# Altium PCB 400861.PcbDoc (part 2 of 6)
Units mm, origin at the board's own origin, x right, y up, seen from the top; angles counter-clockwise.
Board outline 145 x 63.5 mm, 8 copper layers (Top Side, Mid-Layer 1, Mid-Layer 2, Mid-Layer 3, Mid-Layer 4, Mid-Layer 5, Mid-Layer 6, Bottom Side), stack 1.529 mm thick; 284 components, 233 nets, 1158 pads, 3522 vias.
Unrouted connection lines stored in the file: 1.
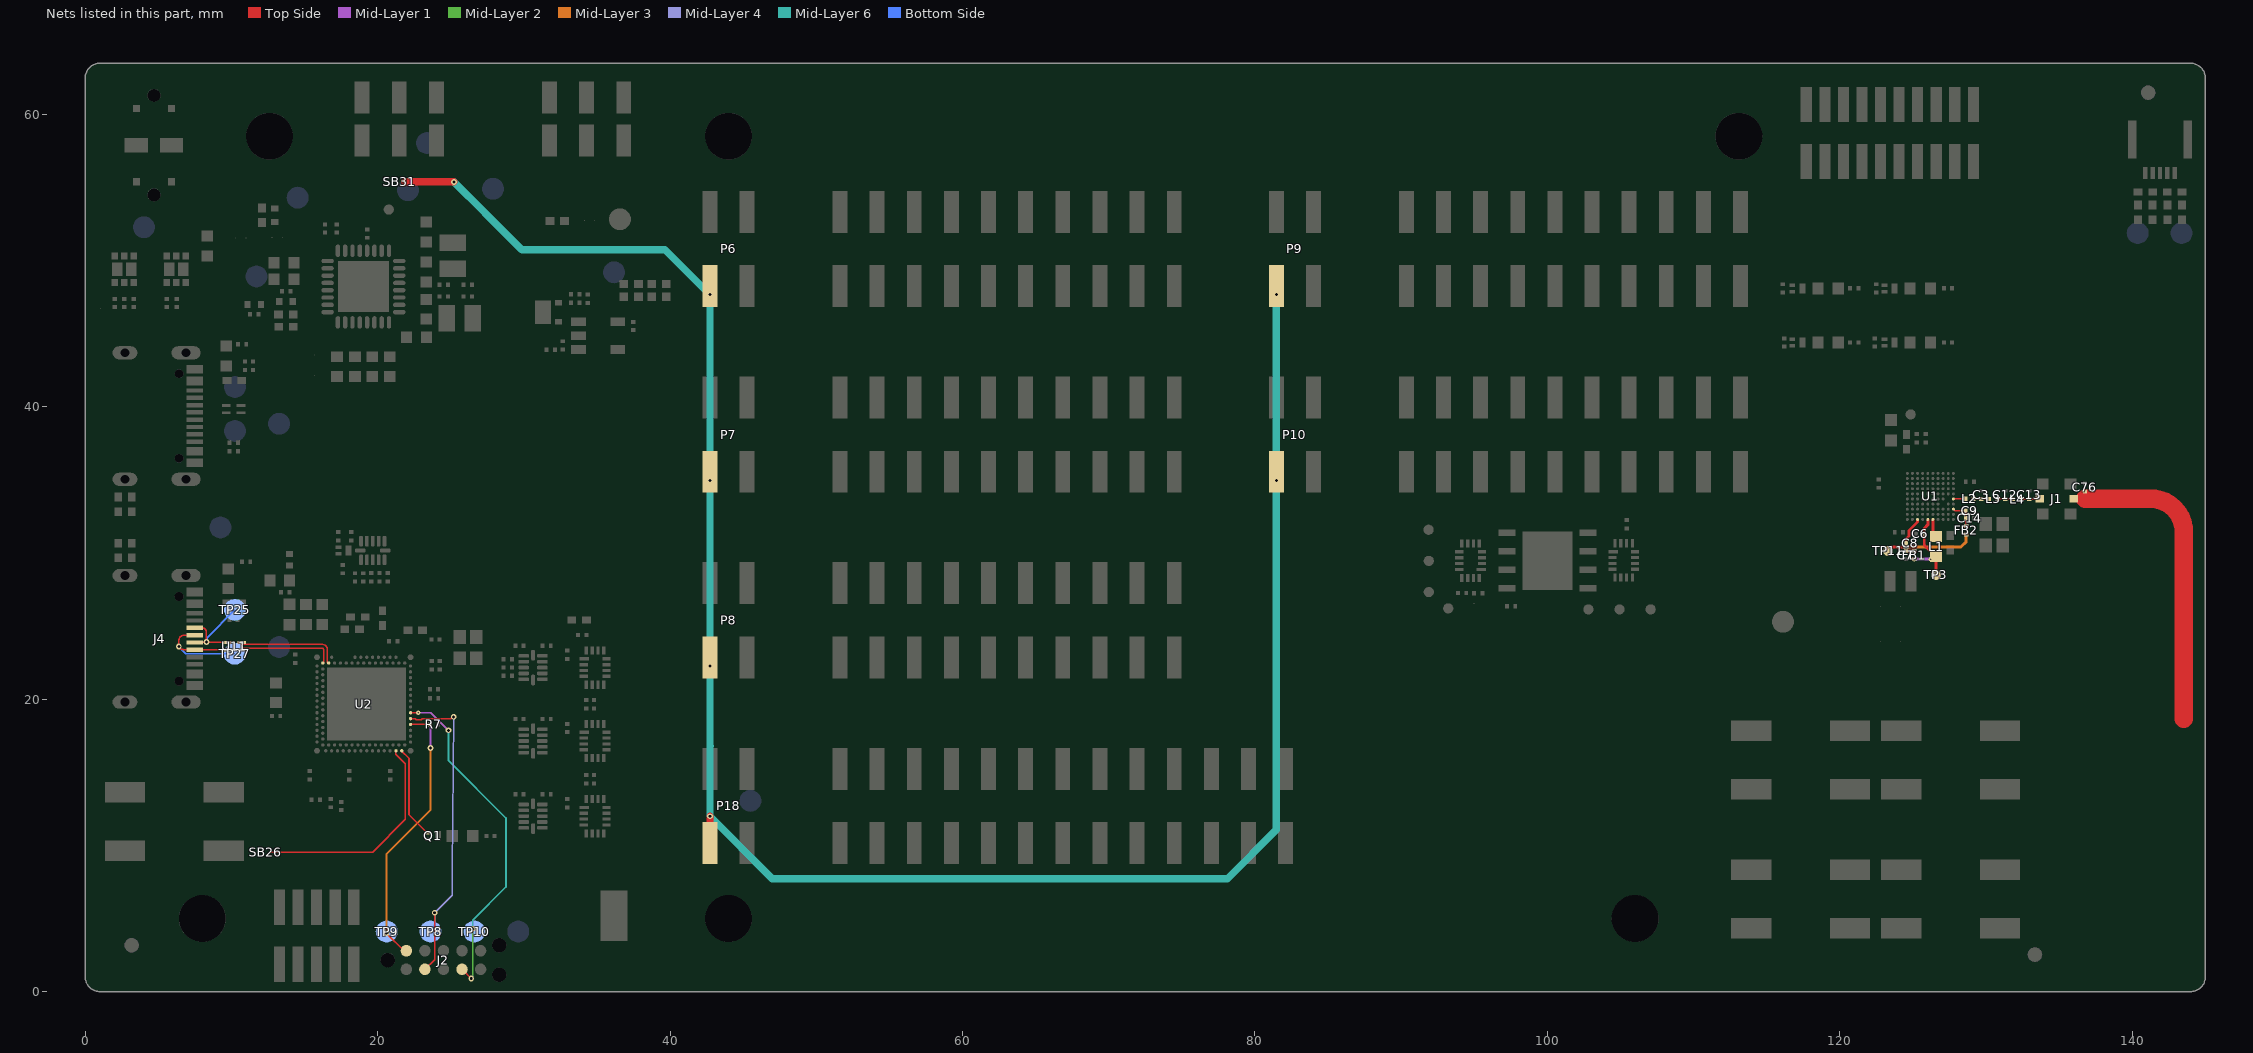
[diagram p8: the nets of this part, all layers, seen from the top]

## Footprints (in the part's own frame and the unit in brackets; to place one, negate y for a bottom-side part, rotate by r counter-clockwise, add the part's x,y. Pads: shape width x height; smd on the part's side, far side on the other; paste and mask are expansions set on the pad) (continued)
SON127P600X80_HS-9N [mm] "SON, 8-Leads, Body 5.00x6.00mm, Pitch 1.27mm, Thermal Pad 4.00x3.40mm, IPC Medium Density"
  rect 1.15x0.45 smd: 1(-2.77,1.905) 2(-2.77,0.635) 3(-2.77,-0.635) 4(-2.77,-1.905) 5(2.77,-1.905) 6(2.77,-0.635) 7(2.77,0.635) 8(2.77,1.905)
  rect 3.4x4 smd paste-1.7: 9(0,0)
  silkscreen extent -3.98,-2.6 3.1,2.67, body extent -3.05,-2.55 3.05,2.55, height 0.8
SOT95P280X145-5N [mm] "SOT23, 5-Leads, Body 2,90x2,80mm, Pitch 0,95mm, IPC Medium Density"
  rect 1x0.6 smd: 1(-1.35,0.95) 2(-1.35,0) 3(-1.35,-0.95) 4(1.35,-0.95) 5(1.35,0.95)
  silkscreen extent -1.45,-1.5 0.45,1.72, body extent -1.5,-1.55 1.5,1.55, height 1.45
Switch-PB-6.2x6.3mm-SMD [mm] "6.2×6.5mm TACT Switch, without ground connector"
  rect 2.75x1.4 smd: 1(-3.375,2) 1(3.375,2) 2(-3.375,-2) 2(3.375,-2)
  silkscreen extent -3,-3 3,3, body extent -3.6,-3.1 3.6,3.1, height 2.5
TC2050-IDC-NLFP [mil]
  round 39 hole 39 unplated: 0(-150,0) 0(150,-40) 0(150,40)
  round 31 smd paste-196.85: 1(-100,-25) 2(-50,-25) 3(0,-25) 4(50,-25) 5(100,-25) 6(100,25) 7(50,25) 8(0,25) 9(-50,25) 10(-100,25)
  Top Side pour cut-out: -100,25 -100,-25 100,-25 100,25
TP_SMD_D0.7mm [mm] "Test point - pad 0.7mm"
  round 0.7 smd paste-5: 1(0,0)
TP_SMD_D1.5mm [mm] "Test point - pad 1.5mm"
  round 1.5 smd paste-5: 1(0,0)
  body extent -0.75,-0.75 0.75,0.75, height 0.05
UFDFN50P120X250X55-8N [mm]
  round 0.025 smd: 1(-0.5,0.75) 4(-0.5,-0.75) 5(0.5,-0.75) 8(0.5,0.75)
  rect 0.6x0.2 smd: 2(-0.5,0.25) 3(-0.5,-0.25) 6(0.5,-0.25) 7(0.5,0.25)
  Top Side region: 0.4,0.85 0.8,0.85 0.8,0.65 0.2,0.65 0.2,1.05 0.4,1.05
  Top Side region: 0.8,-0.85 0.4,-0.85 0.4,-1.05 0.2,-1.05 0.2,-0.65 0.8,-0.65
  Top Side region: -0.2,0.65 -0.8,0.65 -0.8,0.85 -0.4,0.85 -0.4,1.05 -0.2,1.05
  Top Side region: -0.2,-1.05 -0.4,-1.05 -0.4,-0.85 -0.8,-0.85 -0.8,-0.65 -0.2,-0.65
  silkscreen extent -1.08,-1.37 0.6,1.37, body extent -0.6,-1.25 0.6,1.25, height 0.6
WEE_3x4.5mm [mm]
  silkscreen extent -1.47,-2.7 1.47,1.71
XQFN40P180X260X50-16N [mm] "QFN, 16-Leads, Body 1.80x2.60mm, Pitch 0.40mm, IPC Medium Density"
  rect 0.65x0.22 smd paste-0.02 mask+0.05: 1(-0.725,0.6)
  rect 0.55x0.22 smd paste-0.02 mask+0.05: 2(-0.775,0.2) 3(-0.775,-0.2) 4(-0.775,-0.6) 9(0.775,-0.6) 10(0.775,-0.2) 11(0.775,0.2) 12(0.775,0.6)
  rect 0.22x0.55 smd paste-0.02 mask+0.05: 5(-0.6,-1.175) 6(-0.2,-1.175) 7(0.2,-1.175) 8(0.6,-1.175) 13(0.6,1.175) 14(0.2,1.175) 15(-0.2,1.175) 16(-0.6,1.175)
  silkscreen extent -1.36,1.12 -1.26,1.22, body extent -0.9,-1.3 0.9,1.3, height 0.55
XTAL_2012 [mm] "XTAL SMD 2.0 x 1.2 mm"
  rect 0.75x1.4 smd: 1(-0.725,0) 2(0.725,0)
  body extent -1,-0.61 1,0.61, height 0.6

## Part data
C1 C2 C5: library part C0201-100n-10V-X7R, "Capacitor, X7R, ±10%, 10V", Manufacturer=N.A., Part number NEMS=100200469
C3 C12: library part C0201-2.0p-HQ-Murata, "Capacitor, NP0, ±0.05pF, 25V", Manufacturer=Murata, Manufacturer Part Number=GJM0335C1E2R0WB01, Part number IPS=00000001775, Part number NEMS=100200419, Part number Norautron=N.A.
C4: library part C0402-10µF-6.3V-X6S, "Capacitor, X6S, ±20%, 6.3V", Manufacturer=N.A., Part number NEMS=100200478
C6 C7 C10: library part C0201-2µ2-10V-X5R-GRM033R61A225KE47, "Capacitor, Ceramic, 2.2µF 10V X5R 0201,±10%", Manufacturer=Murata, Manufacturer Part Number=GRM033R61A225KE47D, Part number IPS=N.A., Part number NEMS=100200496, Supplier Part Number 1=81-GRM033R61A225KE7D
C8: library part C0201-10n-6.3V-X7R, "Capacitor, X7R, 6.3V", Manufacturer=Murata, Manufacturer Part Number=GRM033R70J103KA01D, Part number IPS=N.A., Part number NEMS=100200407, Supplier Part Number 1=490-1262-1-ND
C9: library part C0201-3.9p-HQ-Murata, "Capacitor, NP0, ±0.05pF, 25V", Manufacturer=Murata, Manufacturer Part Number=GJM0333C1E3R9WB01, Part number IPS=N.A., Part number NEMS=100200424,100200024
C11: library part C0402-4µ7-10V-X5R, "Capacitor, X5R, 10V", Manufacturer=Murata, Manufacturer Part Number=GRM155R61A475MEAAD, Part number IPS=N.A., Part number NEMS=100200415, Supplier Part Number 1=490-14306-1-ND
C13: library part C0201-N.C., "Not mounted", Manufacturer=N.A., Part number NEMS=100200001
C14: library part C0201-2µ2-2.5V-X6T-GRM033D80E225ME47D, "Capacitor, Ceramic, 2.2µF 2.5V X6T 0201,±20%", Manufacturer=Murata, Manufacturer Part Number=GRM033R61A225KE47, Part number IPS=N.A., Part number NEMS=100200527, Supplier Part Number 1=81-GRM033D80E225ME7D
C15 C16 C17 C21 C22 C23 C24 C28 C31 C35 C37 C47 C49 C54 C58 C63 C66 C69 C72 C77: library part C0201-100n, "Capacitor, X5R, ±10%, 100nF, 16V", Manufacturer=N.A., Part number IPS="00000001248, 00000002505", Part number NEMS=100200078, Part number Norautron=262071862
C18 C19 C25 C32 C87: library part C0402-1µ0-6.3V-X5R-10%, "Capacitor, X5R, ±10%, 6.3V", Manufacturer=N.A., Part number NEMS=100200498, Part number Norautron=26207137
C20: library part C0201-2n2, "Capacitor, X7R, ±10%, 10V", Manufacturer=N.A., Part number IPS=00000001778, Part number NEMS=100200060, Part number Norautron=26470002
C26: library part C0603-2µ2-6.3V-X7R, "Capacitor, X7R, ±10%, 2.2µF, 6.3V", Manufacturer=N.A., Part number NEMS=100200272
C27 C29: library part C0603-4µ7-10V-X7S, "Capacitor, X7S, ±10%, 10V", Manufacturer=N.A., Part number IPS=00000001779, Part number NEMS=100200351, Supplier Part Number 1=445-14258-1-ND
C30: library part C0603-4µ7-6.3V-X7R, "Capacitor, X7R, ±10%, 6.3V", Manufacturer="Samsung Electro-Mechanics America", Manufacturer Part Number=CL10B475KQ8NQNC, Part number IPS=00000002541, Part number NEMS=100200350, Part number Norautron=N.A., Supplier Part Number 1=1276-2087-1-ND
C33 C50 C51 C52: library part C0603-10µ-10V-X5R, "Capacitor, Ceramic, X5R, ±20%, 10V", Manufacturer=N.A., Part number NEMS=100200481, Part number Norautron=262085341
C34 C36 C38: library part C0402-4µ7-10V-X5R-GRM155R61A475MEAAD, "Capacitor, X5R, ±20%, 10V", Manufacturer=Murata, Manufacturer Part Number=GRM155R61A475MEAA, Part number IPS=N.A., Part number NEMS="100200549, 100200415", Supplier Part Number 1=490-14306-1-ND
C39: library part C0402-1µ0-10V-X5R, "Capacitor, Ceramic, X5R, ±10%, 10V", Manufacturer=N.A., Part number NEMS=100200482
C40 C41 C44 C45 C46 C48: library part C0603-10µ-10V-X7T-GRM188D71A106MA73, "Capacitor, X7T, ±20%, 10V", Manufacturer=Murata, Manufacturer Part Number=GRM188D71A106MA73D, Part number IPS=00000004696, Part number NEMS=100200414, Part number Norautron=N.A., Supplier Part Number 1=490-7200-1-ND
C42 C43: library part C0201-1n0, "Capacitor, X7R, ±10%, 25V", Manufacturer=N.A., Part number IPS=00000003206, Part number NEMS=100200056
C55: library part C0603-4µ7-25V-X5R, "Capacitor, X5R, ±10%, 25V", Manufacturer=Murata, Manufacturer Part Number=GRM188R61E475KE11D, Part number IPS=N.A., Part number NEMS=100200352, Supplier Part Number 1=490-7203-1-ND
C56 C57: library part C0402-300p, "Capacitor, C0G, ±5%, 50V", Manufacturer=N.A., Part number IPS=00000007788, Part number NEMS=100200155, Supplier Part Number 1=490-3234-1-ND
C59 C60 C61 C62 C78 C79 C80 C81 C82 C83 C84 C85 C86 C88 C89: library part C0201-100n, "Capacitor, X5R, ±10%", Manufacturer=N.A., Part number IPS="00000001248, 00000002505", Part number NEMS=100200078, Part number Norautron=262071862
C64 C70: library part C0402-1µ0-16V-X5R, "Capacitor, Ceramic, X5R, ±10%, 16V", Manufacturer=Murata, Manufacturer Part Number=GRT155R61C105KE01D, Part number IPS=N.A., Part number NEMS=100200452, Supplier Part Number 1=490-12255-1-ND
C65 C71: library part C0201-10n, "Capacitor, X7R, ±10%, 10nF, 10V", Manufacturer=N.A., Part number IPS=00000003480, Part number NEMS=100200067, Part number Norautron=26621779
C67 C68 C73 C74: library part C0402-10n, "Capacitor, X7R, ±10%", Manufacturer=N.A., Part number IPS=00000007784, Part number NEMS=100200173
C76: library part C0201-1.0p_RF, "RF Chip Cap 0201", Manufacturer=N.A., Part number NEMS=100200085
FB1 FB2: library part FB0201-120R@100M-200mA-BLM03AG121SN1D, "Ferrite Bead, 120 Ohm @ 100MHz, 200mA, 500 mOhm Max", Manufacturer=Murata, Manufacturer Part Number=BLM03AG121SN1D, Part number IPS=N.A., Part number NEMS=100300419, Supplier Part Number 1=490-5622-1-ND
FB3 FB4: library part FB0603-120R@100MHz-3000mA, "Ferrite Bead, 120 Ohm @ 100MHz, 3000mA, 30 mOhm Max", Manufacturer=Murata, Manufacturer Part Number=BLM18KG121TN1D, Part number IPS=N.A., Part number NEMS=100300103, Supplier Part Number 1=490-5254-1-ND
FB5: library part FB0402-120R@100MHz-1200mA-BLM15EX121SN1_C2, "Ferrite Bead, 120 Ohm @ 100MHz, 1200mA, 75 mOhm Max", Manufacturer=Murata, Manufacturer Part Number=BLM15EX121SN1, Part number IPS=N.A., Part number NEMS="100300431, 100300416", Supplier Part Number 1=490-16509-1-ND
Fid1 Fid2 Fid3: library part Fid-Mark, "Fiducial Mark", Manufacturer=N.A., Part number NEMS=100500073
H1 H2 H3 H4 H5 H6: library part MountingHole_3.2_M3, "Mounting hole, 3.2mm, M3, no annular", Manufacturer=N.A., Part number NEMS=101200008
J1: "Coaxial Connector with Switch", Manufacturer=Murata, Part number IPS=00000009955, Part number NEMS=100500400, Part number Norautron=26030338, Supplier Part Number 1=490-4981-1-ND
J2: library part TC2050-IDC-NLFP, "CBL PLUG-OF-NAILS 10-PIN", Manufacturer="Tag-Connect LLC", Part number IPS=N.A., Part number NEMS=100500463, Supplier Part Number 1=TC2050-IDC-NL-ND
J3 J4: library part 80259-1021, "USB-C Receptacle, 16 Pin, USB 2.0", Manufacturer="Bellweather Electronic Corp.", Part number IPS=N.A., Part number NEMS=100500830
J5: library part FPC_05P-0.5mm-RA-SMD, "0.5mm FPC, 5P,Right Angle SMT,Double Contact,H=1.2mm,White, Tin plated", Manufacturer=WCON, Manufacturer Part Number=5141-05RZDNWR03, Part number IPS=N.A., Part number NEMS=100500528
JP1: library part "SHUNT JUMPER 2.54mm Black Vertical", "Shunt Jumper 2.54mm Black, open top", Manufacturer=WCON, Manufacturer Part Number=3710-6001OS0B05, Part number IPS=N.A., Part number NEMS=100500728
L1: library part L0603-4µ7-MLZ1608M4R7WT000, "Inductor, 120mA, ±20%, 0.65R", Manufacturer="TDK Corporation", Manufacturer Part Number=MLZ1608M4R7WT000, Part number IPS=N.A., Part number NEMS=100300440, Supplier Part Number 1=445-6390-2-ND
L2 L4: library part L0201-2n7-HQ-Murata, "Inductor, 600mA, ±0.1ｎH, 120mOhm", Manufacturer=Murata, Manufacturer Part Number=LQP03HQ2N7B02, Part number IPS=00000001753, Part number NEMS=100300214, Part number Norautron=N.A., Supplier Part Number 1=490-13909-1-ND
L3: library part L0201-4n7-Wirewound-Murata, "Inductor, 620mA, ±5%, 90mOhm, Q=45", Manufacturer=Murata, Manufacturer Part Number=LQW03AW4N7J00, Part number IPS=00000001790, Part number NEMS=100300175, Part number Norautron=N.A., Supplier Part Number 1=490-13838-1-ND
L5 L6: library part L0806-2µ2-2500mA-73mOhm-CIGT201610EH2R2MNE, "Inductor, Irms=2.5A, Isat=2.9A, ±20%, DCR=73mΩ", Manufacturer="Samsung Electro-Mechanics America", Manufacturer Part Number=CIGT201610EH2R2MNE, Part number IPS=N.A., Part number NEMS=100300400, Part number Norautron=26521789, Supplier Part Number 1=1276-6901-1-ND
LABEL1: library part Label_12x12, "PCA version label, stick-on, 12x12mm", Manufacturer="Ellco Etikett", Manufacturer Part Number=A33512‐01, Part number IPS=N.A., Part number NEMS=101200028
LD1 LD2 LD3 LD4 LD5: library part "VS 25C7M5", "LED, Green, 0603, 573nm, Vf=2.0V, 24mcd, - 40 to +85°C", Manufacturer="Victory Electronics", Part number IPS="00000001274, 00000009961", Part number NEMS=101400097, Part number Norautron=26313411, Supplier Part Number 1=N.A.
LOGO1: library part "WEEE Symbol 3x4.5mm", "WEEE Directive symbol", Manufacturer=N.A., Part number NEMS=101100006
LOGO3: "Segger logo, small size", Manufacturer=N.A., Part number NEMS=101100004
P1 P2 P3 P4 P5: library part "Pin Header 2x10 SMD, 2.54mm", "Pin Header 2x10, 2.54mm (100mil) SMD", Manufacturer=WCON, Manufacturer Part Number=1125-1210S0M116CR09, Part number IPS=N.A., Part number NEMS=100500738
P6 P7 P8 P9 P10 P18: "Pin Header 2x2, SMD, 2.54mm (100mil)", Manufacturer=WCON, Manufacturer Part Number=1125-1202S0M116CR03, Part number IPS=N.A., Part number NEMS=100500770
P11 P13: library part "Pin Header 2x5 SMD, 1.27mm, KS", "Pin Header 2x5, 1.27mm (50mil), SMD, Keying Shroud", Manufacturer=WCON, Manufacturer Part Number=3132-10MS0BK00R5, Part number IPS=N.A., Part number NEMS=100500261
P12: library part "Pin Header 2x10 SMD, 1.27mm, KS, N.C.", "Pin Header 2x10, 1.27mm (50mil), SMD, Keying Shroud", Manufacturer=WCON, Manufacturer Part Number=3132-20MS0BK00R1, Part number IPS=N.A., Part number NEMS=100500279
P14 P16: library part "Pin List 1x3 SMD", "Pin List 1x3, 2.54mm (100mil), SMD", Manufacturer=WCON, Manufacturer Part Number=1125-1103S0M116CR04, Part number IPS=N.A., Part number NEMS=100500306, Part number Norautron=26470016
P17: library part "Pin Header 2x13 SMD, 2.54mm", "Pin Header 2x13, 2.54mm (100mil) SMD", Manufacturer=WCON, Manufacturer Part Number=1125-1213S0M116CR09, Part number IPS=N.A., Part number NEMS=100500908
Q1 Q4 Q5 Q6 Q7 Q9: "N-Channel MOSFET, 20V, 1A, 470mOhm, 400mW, -55°C ~ 150°C", Manufacturer="Rohm Semiconductor", Part number IPS=00000009976, Part number NEMS=101300132, Part number Norautron=26320026, Supplier Part Number 1=RV2C010UNT2LCT-ND
Q2 Q3: "Dual P-Channel MOFET, 3.8A, 90mOhm max, 1.4W", Manufacturer="Micro Commercial Components", Part number IPS=N.A., Part number NEMS=101300199, Supplier Part Number 1=MCM2301-TPMSCT-ND
Q8: library part PBSS4330PA,115, "30V, 3A, 2.1W, G=270, NPN Transistor", Manufacturer=Nexperia, Part number IPS=N.A., Part number NEMS=101300184, Supplier Part Number 1=1727-5112-1-ND‎
R1 R11: library part R0603-2R2, "RES 2.2 OHM 1% 1/10W 0603", Manufacturer=N.A., Part number NEMS=100100736
R2 R25 R26 R27 R28: library part R0201-220, "Resistor, ±1%, 0.05W", Manufacturer=N.A., Part number IPS=00000000863, Part number NEMS=100100032, Part number Norautron=26107014
R3 R4: library part R0402-N.C., "Not mounted", Manufacturer=N.A., Part number NEMS=100100281
R5: library part R0201-560, "Resistor, ±1%, 0.05W", Manufacturer=N.A., Part number NEMS=100100038
R6 R12 R13 R47 R48 R49 R50: library part R0201-150, "Resistor, ±1%, 0.05W", Manufacturer=N.A., Part number IPS=00000001420, Part number NEMS=100100029
R7 R9 R10 R19 R23 R35 R36 R37 R38 R39 R40 R56: library part R0201-100k, "Resistor, ±1%, 0.05W", Manufacturer=N.A., Part number IPS=00000001419, Part number NEMS=100100080, Part number Norautron=26108487
R8: library part R0201-47R, "Resistor, ±1%, 0.05W", Manufacturer=N.A., Part number IPS=00000004794, Part number NEMS=100100022, Part number Norautron=26108300
R14 R16 R33 R34 R42 R43 R44 R51: library part R0402-0R, "Resistor, ±5%, 0.063W", Manufacturer=N.A., Part number IPS=00000007128, Part number NEMS=100100109, Supplier Part Number 1=146-9661
R15: library part R0402-10R, "Resistor, ±1%, 0.063W", Manufacturer=N.A., Part number NEMS=100100126, Supplier Part Number 1=173-8824
R17: library part R0201-47k, "Resistor, ±1%, 0.05W", Manufacturer=N.A., Part number IPS=00000001423, Part number NEMS=100100076
R18: library part R0201-4k7, "Resistor, ±1%, 0.05W", Manufacturer=N.A., Part number IPS=00000001706, Part number NEMS=100100061
R20 R24 R29 R30 R31 R32 R41: library part R0201-1M0, "Resistor, ±1%, 0.05W", Manufacturer=N.A., Part number IPS=00000001418, Part number NEMS=100100093, Part number Norautron=26107108
R21 R22 R53: library part R0201-10k, "Resistor, ±1%, 0.05W", Manufacturer=N.A., Part number IPS=00000001255, Part number NEMS=100100065, Part number Norautron=26107101
R45 R46: library part R0201-5k1, "Resistor, ±1%, 0.05W", Manufacturer=N.A., Part number NEMS=100100565, Part number Norautron=26192285
R52 R54: library part R0201-0R, "Resistor, ±5%, 0.05W", Manufacturer=N.A., Part number IPS=00000003245, Part number NEMS=100100001
R55: library part R0201-33k, "Resistor, ±1%, 0.05W", Manufacturer=N.A., Part number IPS=00000001708, Part number NEMS=100100073
SB1 SB2 SB5 SB23 SB26 SB28 SB29: library part "Solderbridge Shorted", "Shorted Solderbridge", Manufacturer=N.A., Part number NEMS=100500459
SB3 SB4 SB17 SB19 SB20 SB21 SB22 SB24 SB25 SB27 SB30: Manufacturer=N.A., Part number NEMS=100500458
SB6 SB18 SB31: library part "Solderbridge Shorted Power", "Shorted Solderbridge Power", Manufacturer=N.A., Part number NEMS=100500460
SW1 SW2 SW3 SW4 SW6: library part Switch-PB-6.2x6.3mm-SMD, "Tactile Switch, SPNO, SMD, 160gf, 6.2x6.3x2.5mm", Manufacturer=Dailywell, Manufacturer Part Number=TS604VM1-025BR-R, Part number IPS=00000007812, Part number NEMS="101500001, 101500133", Part number Norautron=N.A.
SW5: library part Switch-Slide-RA-J-Lead-DPDT-8.5x3.5mm_C&K, "SMD slide Switch (ON-ON)", Manufacturer=C&K, Manufacturer Part Number=JS202011JAQN, Part number IPS=00000007811, Part number NEMS=101500037, Part number Norautron=N.A., Supplier Part Number 1=CKN10722CT-ND
TP1 TP2 TP4 TP5 TP6 TP7 TP8 TP9 TP10 TP14 TP16 TP17 TP18 TP19 TP20 TP21 TP22 TP23 TP24 TP25 TP26 TP27 TP28: library part TP_SMD_Ø1.5MM, "1.5mm circular SMD testpad", Manufacturer="Nordic Semiconductor", Manufacturer Part Number=N.A., Part number NEMS=100500477
TP3 TP11 TP12 TP13 TP29 TP30 TP31 TP32 TP33 TP34 TP35: library part TP_SMD_Ø0.7MM, "0.7mm circular SMD testpad", Manufacturer="Nordic Semiconductor", Manufacturer Part Number=N.A., Part number NEMS=100500474
TP15: library part "TP - S1751-46R", "PC TEST POINT TIN SMD L", Manufacturer=Harwin, Manufacturer Part Number=S1751-46R, Part number IPS=N.A., Part number NEMS=100500525, Supplier Part Number 1=952-1478-1-ND
U1: library part nRF54LM20-PAAA, "nRF54 series BLE", Manufacturer="Nordic Semiconductor", Part number IPS=N.A., Part number NEMS=102000394
U2: library part nRF5340-QKAAD0, "Multi-protocol Bluetooth Low Energy, IEEE 802.15.4, ANT and 2.4GHz proprietary system-on-chip", Manufacturer="Nordic Semiconductor", Part number IPS=N.A., Part number NEMS=102000216, Part number Norautron=NOD26470035
U3: "Li-Ion/Li-Polymer USB-C battery charger with high efficiency buck regulators, LDOs or load switches, LED drivers, TWI and VBUSOUT", Manufacturer="Nordic Semiconductor", Part number IPS=N.A., Part number NEMS=102000291
U4: library part MX25R6435FZNIL0, "Ultra low power, 64M-bit, serial multi I/O flash memory", Manufacturer=Macronix, Part number IPS=00000004370, Part number NEMS=101900438, Part number Norautron=N.A.
U5 U6 U7: "Low-Capacitance, 1:1 (SPST) 4-Channel, analog switch", Manufacturer="Texas Instruments", Manufacturer Part Number=TMUX1511RSVR, Part number IPS=N.A., Part number NEMS=101900847, Supplier Part Number 1=296-53443-2-ND
U8 U12 U13 U14: library part TXB0104RUTR, "4-Bit Bidirectional Level-Shifter/Voltage Translator with Automatic Direction Sensing", Manufacturer="Texas Instruments", Part number IPS=N.A., Part number NEMS=101900856, Supplier Part Number 1=296-25888-2-ND
U9: library part TLV271CW5-7, "Dual rail to rail CMOS Amplifier", Manufacturer="Diodes Incorporated", Part number IPS=N.A., Part number NEMS=101900398, Supplier Part Number 1=TLV271CW5-7DICT-ND
U10 U11: "2 Line Common mode filter with ESD protection for USB 2.0 interface, DCRmax = 4Ohm, -40°C ~ 125°C", Manufacturer=STMicroelectronics, Part number IPS=N.A., Part number NEMS=100800034, Supplier Part Number 1=497-13420-2-ND
U15 U16: "Low-Capacitance, 2:1 (SPDT) 4-Channel, analog switch", Manufacturer="Texas Instruments", Manufacturer Part Number=TMUX1574RSVR, Part number IPS=N.A., Part number NEMS=101900850, Supplier Part Number 1=296-53445-2-ND
X1: library part XTAL_SMD2016_32MHz_8pF_Kyocera, "XTAL SMD 2016, 32MHz, Cl=8pF, Tot: ±40ppm", Manufacturer=Kyocera, Manufacturer Part Number=CX2016DB32000D0WZRC1, Part number IPS=00000007827, Part number NEMS=101600039, Part number Norautron=26511136, Supplier Part Number 1=1253-1586-1-ND
X2: library part XTAL_SMD2012_32.768kHz_9pF_TXC, "XTAL SMD 2012, 32.768kHz, 9pF, ±20ppm", Manufacturer="TXC Corporation", Manufacturer Part Number=9HT11-32.768KDZC-T, Part number IPS=N.A., Part number NEMS=101600107, Supplier Part Number 1=887-1426-2-ND
X3: library part XTAL_SMD2016_32MHz_8pF_Golledge, "XTAL SMD 2016, 32MHz, Cl=8pF, Tol: ±10ppm, Stab: ±15ppm", Manufacturer=Golledge, Manufacturer Part Number=MP06003, Part number IPS=00000001431, Part number NEMS=101600041, Part number Norautron=N.A.

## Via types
v1: diameter 0.4, hole 0.2, Top Side to Bottom Side, tented both sides, 2426 vias
v2: diameter 0.3, hole 0.1, Top Side to Mid-Layer 1, tented both sides, 299 vias
v3: diameter 0.4, hole 0.2, Mid-Layer 3 to Mid-Layer 4, tented both sides, 197 vias
v4: diameter 0.3, hole 0.1, Mid-Layer 1 to Mid-Layer 2, tented both sides, 197 vias
v5: diameter 0.3, hole 0.1, Mid-Layer 2 to Mid-Layer 3, tented both sides, 91 vias
v6: diameter 0.3, hole 0.1, Mid-Layer 4 to Mid-Layer 5, tented both sides, 81 vias
v7: diameter 0.3, hole 0.1, Mid-Layer 2 to Mid-Layer 3, 71 vias
v8: diameter 0.2, hole 0.1, Top Side to Mid-Layer 1, tented both sides, 64 vias
v9: diameter 0.2, hole 0.1, Mid-Layer 1 to Mid-Layer 2, tented both sides, 41 vias
v10: diameter 0.2, hole 0.1, Mid-Layer 2 to Mid-Layer 3, 19 vias
v11: diameter 0.2, hole 0.1, Mid-Layer 2 to Mid-Layer 3, tented both sides, 14 vias
v12: diameter 0.3, hole 0.1, Mid-Layer 5 to Mid-Layer 6, tented both sides, 12 vias
v13: diameter 0.2, hole 0.1, Mid-Layer 1 to Mid-Layer 2, 4 vias
v14: diameter 0.3, hole 0.1, Top Side to Mid-Layer 1, tented top, 3 vias
v15: diameter 0.2, hole 0.1, Top Side to Mid-Layer 1, tented top, 2 vias
v16: diameter 0.225, hole 0.1, Mid-Layer 1 to Mid-Layer 2, tented both sides, 1 vias

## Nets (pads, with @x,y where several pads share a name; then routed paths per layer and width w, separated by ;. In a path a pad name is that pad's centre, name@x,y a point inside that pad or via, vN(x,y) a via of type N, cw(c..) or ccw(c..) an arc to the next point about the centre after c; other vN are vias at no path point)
5V0:CONN: P6.1 P7.1 P8.1 P9.1 P10.1 P18.1 SB31.1 | length 140.1
  Top Side w0.5: SB31.1@21.851,55.395 25.212,55.395 v1(25.216,55.39) ; P18.1@42.73,10.16 v1(42.73,11.998)
  Mid-Layer 6 w0.5: v1@25.212,55.394 27.36,53.257 ; 27.367,53.25 29.865,50.752 39.647,50.752 v1(42.73,47.67) v1(42.73,34.97) v1(42.73,22.27) 42.73,16.834 ; 42.763,16.8 42.73,16.834 ; v1(81.465,47.67) v1(81.465,34.97) 81.465,11.078 78.121,7.734 46.995,7.734 v1(42.73,11.998) 42.73,16.834
ANT: C76.2 J1.3 | length 21.6
  Top Side w0.4: J1.3@135.997,33.712 136.783,33.712
  Top Side w1.27: 136.783,33.712 141.401,33.712 ; 141.283,33.716 cw(c141.283,31.471) 143.527,31.471 ; 143.524,18.662 143.524,31.353
ant:1: L2.1 U1.E1 | length 0.8
  Top Side w0.102: U1.E1@127.77,33.7 128.586,33.7 L2.1@128.587,33.702
ant:2: C3.2 L2.2 L3.1 | length 1.1
  Top Side w0.102: L2.2@129.157,33.702 130.219,33.702 L3.1@130.22,33.7
ant:3: C12.2 L3.2 L4.1 | length 1.1
  Top Side w0.102: L3.2@130.79,33.7 131.842,33.7 L4.1@131.849,33.694
ant:4: C13.2 J1.1 L4.2 | length 1.3
  Top Side w0.102: L4.2@132.419,33.694 J1.1@133.633,33.694 ; J1.1@133.633,33.694 ccw(c133.633,33.757) J1.1@133.677,33.712 133.659,33.694 J1.1@133.633,33.694
DBGR_BUTTON: SB26.2 U2.AL27 | length 15.1
  Top Side w0.1: SB26.2@12.7,9.55 19.65,9.55 21.9,11.8 21.9,15.6 21.25,16.25 U2.AL27@21.25,16.475
DBGR_CON_N: J4.A7 J4.B7 TP25.1 U11.2 | length 6.9
  Top Side w0.099: J4.A7@7.485,23.884 7.486,23.883 U11.2@9.7,23.883 ; J4.B7@7.485,24.884 7.998,24.884 cw(c7.998,24.598) 8.2,24.8 cw(c7.995,24.595) 8.285,24.595 v1(8.285,23.906)
  Bottom Side w0.099: v1(8.285,23.906) 8.339,23.96 8.339,24.218 TP25.1@10.236,26.115
DBGR_CON_P: J4.A6 J4.B6 TP27.1 U11.3 | length 9.1
  Top Side w0.099: J4.A6@7.485,24.384 6.784,24.384 ccw(c6.784,24) 6.4,24 6.4,23.7 ccw(c6.7,23.7) 6.7,23.4 7.485,23.4 ccw(c7.527,23.443) 7.527,23.383 U11.3@9.7,23.383
  Bottom Side w0.099: v1(6.4,23.6) 6.885,23.115 TP27.1@10.226,23.115
DBGR_LED: Q1.1 U2.AL29 | length 6.3
  Top Side w0.125: U2.AL29@21.65,16.451 22.144,15.957 22.144,12.107 23.375,10.875 Q1.1@23.422,10.875
DBGR_N: U2.B4 U11.7 | length 7.1
  Top Side w0.099: U11.7@10.7,23.883 ccw(c10.822,23.883) 10.822,23.761 16.189,23.761 cw(c16.189,23.394) 16.556,23.394 16.556,22.57 ccw(c16.65,22.57) U2.B4@16.65,22.475
DBGR_P: U2.B2 U11.6 | length 6.7
  Top Side w0.099: U11.6@10.7,23.383 cw(c10.822,23.383) 10.822,23.505 16.189,23.505 cw(c16.189,23.394) 16.3,23.394 16.3,22.525 cw(c16.25,22.525) U2.B2@16.25,22.475
DBGR_RESET: J2.10 R7.1 TP9.1 U2.AC31 | length 18.7
  Top Side w0.1: U2.AC31@22.25,18.275 v2(23.565,18.275)
  Top Side w0.125: v1(20.6,4) 21.8,2.8 J2.10@21.96,2.8
  Mid-Layer 1 w0.125: v2(23.565,18.275) 23.609,18.232 v1(23.609,16.673)
  Mid-Layer 3 w0.125: v1(20.6,4) 20.6,9.4 23.609,12.409 v1(23.609,16.673)
DBGR_SWDCLK: J2.4 TP10.1 U2.W31 | length 23.6
  Top Side w0.1: U2.W31@22.25,19.075 v2@22.772,19.075
  Top Side w0.125: J2.4@25.77,1.53 v1(26.4,0.9)
  Mid-Layer 1 w0.1: v2(22.773,19.076) 23.637,19.076 v1(24.837,17.876)
  Mid-Layer 2 w0.125: v1(26.4,0.9) 26.5,1 v1(26.5,4.3)
  Mid-Layer 6 w0.125: v1(24.837,17.876) 24.837,15.814 28.776,11.875 28.776,7.165 26.5,4.889 v1(26.5,4.3)
DBGR_SWDIO: J2.2 TP8.1 U2.AA31 | length 22.5
  Top Side w0.1: U2.AA31@22.25,18.675 22.559,18.675 22.634,18.6 22.966,18.6 23.041,18.675 24.982,18.675 ccw(c24.982,18.775) 25.037,18.692 v1(25.2,18.8) ; J2.2@23.23,1.53 23.9,2.2 v1(23.9,5.4)
  Mid-Layer 4 w0.1: v1(23.9,5.4) 25.112,6.612 25.112,8.333 ; 25.112,8.335 v1(25.2,18.8)
  Bottom Side w0.1: TP8.1@23.616,4.115 ccw(c22.931,4.8) 23.9,4.8 v1(23.9,5.4)
DCC: L1.1 U1.A5 | length 1.3
  Top Side w0.203: U1.A5@126.37,32.3 126.37,31.339 L1.1@126.586,31.123
DECA: C7.2 C8.2 FB1.2 FB2.2 TP11.1 U1.A8 | length 9.1
  Top Side w0.203: TP11.1@123.305,30.145 123.583,30.423 v1(124.529,30.423) ; FB1.2@125.087,30.149 C7.2@124.529,30.149 124.523,30.155 C8.2@124.523,30.677 124.523,30.964 124.732,31.173 124.732,31.541 125.32,32.129 U1.A8@125.32,32.3
  Mid-Layer 3 w0.203: v1(124.529,30.423) 128.298,30.423 128.649,30.774 v2(128.649,31.274)
  other v4: 128.649,31.274
  other v5: 128.649,31.274
DECD: C6.2 FB1.1 L1.2 TP3.1 U1.A6 | length 5.4
  Top Side w0.203: U1.A6@126.02,32.3 126.02,31.929 125.779,31.688 C6.2@125.779,31.312 125.779,30.558 126.58,29.756 TP3.1@126.58,28.507
  Mid-Layer 1 w0.203: v14(125.088,29.585) v14(126.231,29.585)
DECRF: C9.2 C14.2 FB2.1 U1.C1 | length 1.9
  Top Side w0.103: U1.C1@127.77,33 127.884,32.887 C9.2@128.613,32.887 128.613,31.879 FB2.1@128.649,31.843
